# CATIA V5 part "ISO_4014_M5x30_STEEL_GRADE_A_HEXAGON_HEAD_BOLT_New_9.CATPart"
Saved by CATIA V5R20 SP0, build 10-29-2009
Part number: ISO 4014 BOLT M5x30 STEEL GRADE A HEXAGON HEAD.1
Publications: "Mating Face", "Axis"
Bounding box of the stored display mesh (mm): x -30 to 3.65, y -4 to 4, z -4.619 to 4.619
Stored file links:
  E:\设计\180212313林恺昇\ISO_4014_M5x30_STEEL_GRADE_A_HEXAGON_HEAD_BOLT_New_9.CATPart
  d:\Dassault Systemes\B20\win_b64\startup\components\MechanicalStandardParts\EN_Standards\Design_Tables\EN_ISO_4014_GRADES_A_B_HEXAGON_HEAD_BOLT.txt
  C:\Program Files\Dassault Systemes\B20\intel_a\startup\components\MechanicalStandardParts\ISO_Standards\Design_Tables\ISO_4014_GRADES_A_B_HEXAGON_HEAD_BOLT.txt
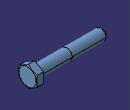
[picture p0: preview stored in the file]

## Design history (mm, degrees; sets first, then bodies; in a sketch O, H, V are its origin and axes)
Parameters
  d_dia = 5 mm
  l_length = 30 mm
  s_nom_across_flats = 8 mm
  k_max_head_depth = 3.65 mm
  dw_min = 6.88 mm
  r_min = 0.2 mm
  c_max = 0.5 mm
  p_pitch = 0.8 mm
  threading = 16 mm
Body1 "PartBody" (main body)
  Sketch1 on yz-plane, origin (0, 0, 0), H (0, 1, 0), V (0, 0, 1)
    circle A1 centre (0, 0) radius 3.44
    radius A1 = 3.44 {= dw_min /2}
  Pad1: profile Sketch1, direction (1, 0, 0), length 0.5 {= c_max}
  Sketch2 on face of Pad1, origin (0.5, 0, 0), H (0, 1, 0), V (0, 0, 1)
    point P1 (4, -2.3094)
    point P2 (4, 2.3094)
    point P3 (0, 4.6188)
    point P4 (-4, 2.3094)
    point P5 (-4, -2.3094)
    point P6 (0, -4.6188)
    point P7 (4, 0)
    line L1 (4, -2.3094) -> (4, 2.3094)
    line L2 (4, 2.3094) -> (0, 4.6188)
    line L3 (0, 4.6188) -> (-4, 2.3094)
    line L4 (-4, 2.3094) -> (-4, -2.3094)
    line L5 (-4, -2.3094) -> (0, -4.6188)
    line L6 (0, -4.6188) -> (4, -2.3094)
    construction line L7 (0, 0) -> (4, 0)
    construction circle A1 centre (0, 0) radius 4.6188
    construction arc A2 centre (-4, -2.3094) radius 4.6188 from (-4, 2.3094) to (0, -4.6188) cw
    construction arc A3 centre (4, 2.3094) radius 4.6188 from (0, 4.6188) to (4, -2.3094) ccw
    point P8 (-4, -2.3094)
    point P9 (4, 2.3094)
    distance L1 L4 = 8 {= s_nom_across_flats}
    horizontal: L7 H
    coincidence: A1 P1, A1 P2, A1 P3, A1 P4, A1 P5, A1 P6, A2 P4, A2 P6, A2 O, P8 P5, A3 P3, A3 P1, A3 O, P9 P2
    midpoint: P7 L1
  Pad2: profile Sketch2, direction (1, 0, 0), length 3.15 {= k_max_head_depth -c_max}
  Sketch3 on zx-plane, origin (0, 0, 0), H (-1, 0, 0), V (0, 0, 1)
    point P1 (-3.65, 3.9821)
    axis line L1 (-94.6904, 0) -> (76.7146, 0)
    reference intersected line E1 through (1000000, 0) direction (-1, 0) from xy-plane
    line L2 (-3.2824, 4.6188) -> (-3.65, 3.9821)
    line L3 (-3.2824, 4.6188) -> (-3.65, 4.6188)
    line L4 (-3.65, 4.6188) -> (-3.65, 3.9821)
    reference projected line E2 (-0.8, 4.6188) -> (-18.28, 4.6188) from edge [face of Pad2 | face of Pad2]
    distance P1 H = 3.9821 {= s_nom_across_flats /2.009}
    distance P1 V = 3.65 {= k_max_head_depth}
    angle L4 L2 = 30
    horizontal: L1 H, L3 H
    coincidence: L1 E1, L3 E2
    vertical: L4 V
  Groove1: profile Sketch3, axis Sketch3.L1, angle 360
  Sketch4 on face of Pad1, origin (0, 0, 0), H (0, -1, 0), V (0, 0, 1)
    circle A1 centre (0, 0) radius 2.5
    radius A1 = 2.5 {= d_dia /2}
  Pad3: profile Sketch4, direction (-1, 0, 0), length 14 {= l_length -threading}
  Sketch5 on face of Pad3, origin (-14, 0, 0), H (0, -1, 0), V (0, 0, 1)
    circle A1 centre (0, 0) radius 2.439
    radius A1 = 2.439 {= d_dia /2.05}
  Pad4: profile Sketch5, direction (-1, 0, 0), length 16 {= threading}
  Chamfer1: length 0.8 {= p_pitch}, angle 45, on face of Pad4
  Fillet1: radius 0.2 {= r_min}, on edge [face of Pad3 | face of Pad1]
  Thread1: diameter 4.878 {= d_dia /1.025}, depth 16 {= threading}, pitch 1, on face of Pad4, from face of Pad4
